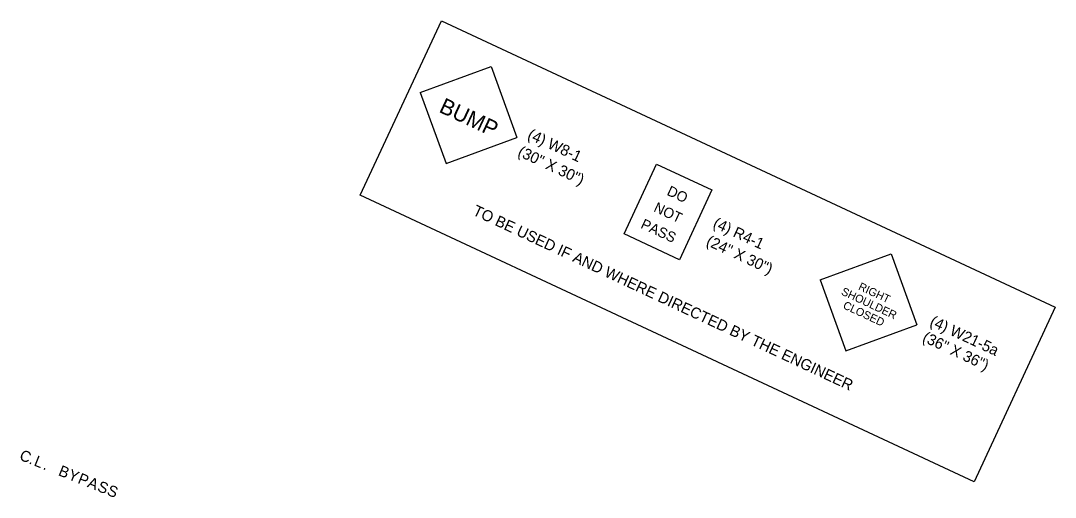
# Model space of a CAD drawing. Extents: x 980546 to 982069, y 1837601 to 1838871.
# Drawn here: x 981118 to 981684, y 1838092 to 1838352 of the extents above; entities that cross this region are included whole.
import ezdxf

# ---------------------------------------------------------------- set-up
doc = ezdxf.new("R2010")
doc.units = 0
for name, color, linetype in [('8', 7, 'Continuous'), ('Level 43', 7, 'Continuous'), ('Level 8', 7, 'Continuous'), ('R_Draft', 7, 'Continuous')]:
    doc.layers.add(name, color=color, linetype=linetype)

msp = doc.modelspace()

# ---------------------------------------------------------------- linework, layer by layer
at = {"layer": 'Level 8'}
for p, q in [((981336.65, 1838312.97), (981375.38, 1838327.06)), ((981375.38, 1838327.06), (981389.48, 1838288.33)), ((981336.65, 1838312.97), (981350.75, 1838274.24)), ((981350.75, 1838274.24), (981389.48, 1838288.33)), ((981555.13, 1838210.78), (981593.86, 1838224.88)), ((981593.86, 1838224.88), (981607.95, 1838186.15)), ((981555.13, 1838210.78), (981569.22, 1838172.05)), ((981569.22, 1838172.05), (981607.95, 1838186.15))]:
    msp.add_line(p, q, dxfattribs=at)
msp.add_lwpolyline([(981496.04, 1838259.78), (981478.27, 1838221.67), (981448.03, 1838235.77), (981465.8, 1838273.88)], close=True, dxfattribs=at)
at = {"layer": 'R_Draft'}
msp.add_lwpolyline([(981348.23, 1838352.13), (981683.57, 1838195.76), (981639.19, 1838100.6), (981303.86, 1838256.97)], close=True, dxfattribs=at)

# ---------------------------------------------------------------- texts
at = {"layer": '8'}
msp.add_text('TO BE USED IF AND WHERE DIRECTED BY THE ENGINEER', height=6, rotation=335, dxfattribs=at).set_placement((981364.9, 1838246.39))
at = {"layer": 'Level 43'}
for s, height, p in [('BUMP', 8.629, (981346.41, 1838302.52)), ('RIGHT', 4.369, (981575.61, 1838205.56)), ('SHOULDER', 4.369, (981566.23, 1838202.86)), ('CLOSED', 4.369, (981567.2, 1838195.34))]:
    msp.add_text(s, height=height, rotation=335, dxfattribs=at).set_placement(p)
at = {"layer": 'Level 8'}
for s, height, p in [('(4) W8-1', 6, (981394.8, 1838287.99)), ('(30" X 30")', 6, (981389.47, 1838278.64)), ('DO', 5.597, (981470.96, 1838257.26)), ('NOT', 5.597, (981463.75, 1838248.27)), ('PASS', 5.596, (981456.66, 1838239.22)), ('(4) R4-1', 6, (981496.11, 1838239.66)), ('(24" X 30")', 6, (981492.4, 1838229.92)), ('(4) W21-5a', 6, (981614.54, 1838186.05)), ('(36" X 36")', 6, (981610.49, 1838177.36))]:
    msp.add_text(s, height=height, rotation=335, dxfattribs=at).set_placement(p)
at = {"layer": 'R_Draft'}
for s, p in [('C', (981117.29, 1838112.75)), ('.', (981122.55, 1838110.64)), ('L', (981125.27, 1838109.55)), ('.', (981130.27, 1838107.55)), ('B', (981138.56, 1838104.23)), ('Y', (981143.82, 1838102.12)), ('P', (981149.17, 1838099.98)), ('A', (981154.43, 1838097.87)), ('S', (981159.87, 1838095.69)), ('S', (981165.14, 1838093.58))]:
    msp.add_text(s, height=6, rotation=338.1679, dxfattribs=at).set_placement(p)

doc.saveas('drawing.dxf')
